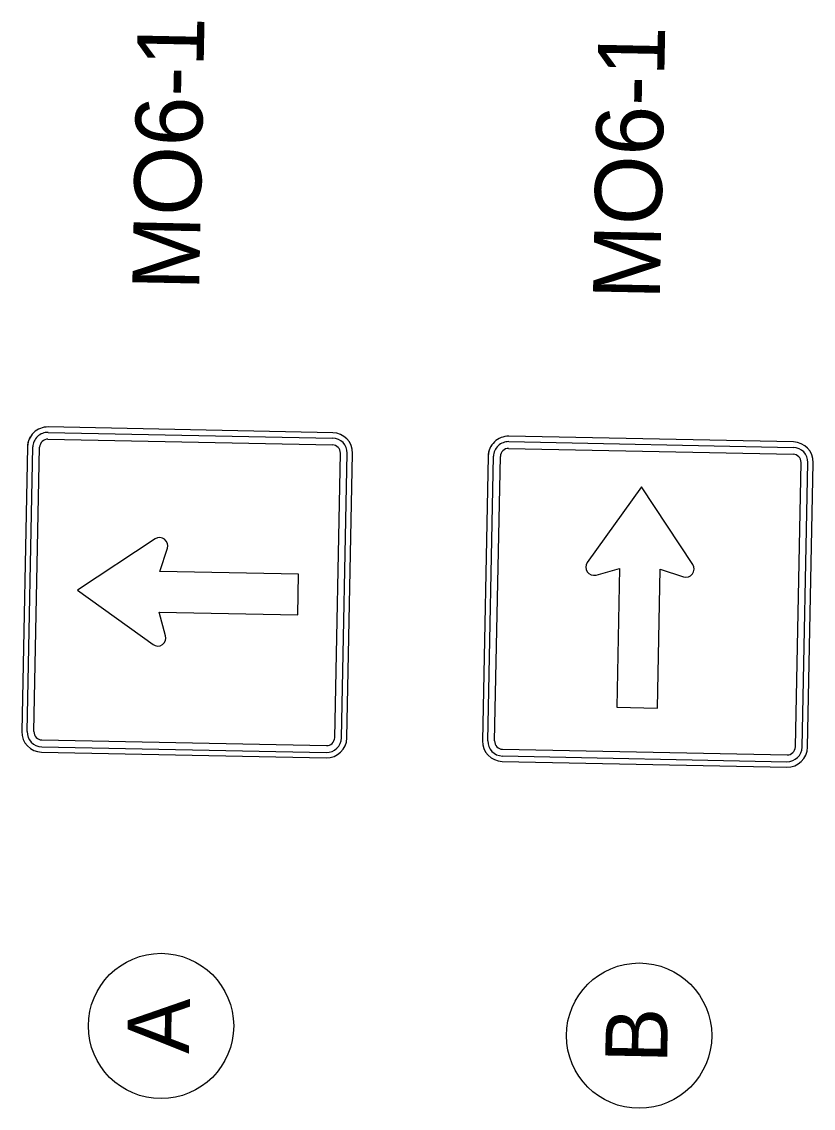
# Model space of a CAD drawing. Extents: x 327762 to 372975, y 127949 to 220470.
# Drawn here: x 357985 to 359582, y 211163 to 213355 of the extents above; entities that cross this region are included whole.
import ezdxf

# ---------------------------------------------------------------- set-up
doc = ezdxf.new("R2010")
doc.units = 0
doc.layers.add('CA-TEXT', color=7, linetype='Continuous')
doc.layers.add('P_SGN_Cell', color=7, linetype='Continuous')

msp = doc.modelspace()

# ---------------------------------------------------------------- linework, layer by layer
at = {"layer": 'CA-TEXT'}
for centre in [(358266, 211329.1), (359230.7, 211309.6)]:
    msp.add_circle(centre, 146.6, dxfattribs=at)
at = {"layer": 'P_SGN_Cell'}
for p, q in [((358038.1, 212526.8), (358612.2, 212515.2)), ((358612.4, 212526.2), (358038.3, 212537.7)), ((358037.8, 212513.1), (358611.9, 212501.6)), ((358967.7, 212508.1), (359541.8, 212496.5)), ((359542, 212507.5), (358967.9, 212519)), ((357996.5, 212497.5), (357984.9, 211923.5)), ((357995.9, 211923.2), (358007.4, 212497.3)), ((358009.5, 211923), (358021.1, 212497)), ((358616.4, 211910.8), (358628, 212484.8)), ((358630.1, 211910.5), (358641.6, 212484.6)), ((358641, 211910.3), (358652.6, 212484.3)), ((358967.4, 212494.4), (359541.5, 212482.8)), ((358926.1, 212478.8), (358914.5, 211904.7)), ((358925.4, 211904.5), (358937, 212478.6)), ((358939.1, 211904.3), (358950.7, 212478.3)), ((359546, 211892), (359557.6, 212466.1)), ((359559.7, 211891.8), (359571.2, 212465.8)), ((359570.6, 211891.5), (359582.2, 212465.6)), ((359235.6, 212417), (359126, 212264.4)), ((359338.9, 212260.1), (359235.6, 212417)), ((358254.2, 212311.7), (358097.3, 212208.4)), ((358263.6, 212246), (358278.8, 212293)), ((358543.7, 212240.4), (358263.6, 212246)), ((358542.1, 212158.4), (358543.7, 212240.4)), ((359143.8, 212239), (359191.3, 212252.3)), ((359191.3, 212252.3), (359185.6, 211972.2)), ((359267.6, 211970.5), (359273.3, 212250.7)), ((359273.3, 212250.7), (359320.2, 212235.5)), ((358097.3, 212208.4), (358249.9, 212098.8)), ((358275.3, 212116.5), (358262, 212164)), ((358262, 212164), (358542.1, 212158.4)), ((359185.6, 211972.2), (359267.6, 211970.5)), ((358025.3, 211892.6), (358599.4, 211881)), ((358025.6, 211906.2), (358599.7, 211894.7)), ((358025.1, 211881.6), (358599.2, 211870.1)), ((358954.9, 211873.9), (359529, 211862.3)), ((358955.2, 211887.5), (359529.3, 211876)), ((358954.7, 211862.9), (359528.8, 211851.4))]:
    msp.add_line(p, q, dxfattribs=at)
for centre, radius, start, end in [((358037.5, 212496.7), 41, 88.8468, 178.8468), ((358037.5, 212496.7), 30.1, 88.8468, 178.8468), ((358611.6, 212485.2), 41, 358.8468, 88.8468), ((358037.5, 212496.7), 41, 149.4503, 178.8468), ((358037.5, 212496.7), 16.4, 88.8468, 178.8468), ((358611.6, 212485.2), 30.1, 358.8468, 88.8468), ((358967.1, 212478), 41, 88.8468, 178.8468), ((358967.1, 212478), 30.1, 88.8468, 178.8468), ((359541.2, 212466.4), 41, 358.8468, 88.8468), ((358611.6, 212485.2), 16.4, 358.8468, 88.8468), ((358967.1, 212478), 41, 149.4503, 178.8468), ((358967.1, 212478), 16.4, 88.8468, 178.8468), ((359541.2, 212466.4), 16.4, 358.8468, 88.8468), ((359541.2, 212466.4), 30.1, 358.8468, 88.8468), ((358263.2, 212298), 16.4, 342.0442, 123.3765), ((359139.3, 212254.8), 16.4, 144.3172, 285.6494), ((359325.2, 212251.1), 16.4, 252.0442, 33.3765), ((358259.5, 212112.1), 16.4, 234.3172, 15.6494), ((358025.9, 211922.6), 41, 178.8468, 268.8468), ((358025.9, 211922.6), 30.1, 178.8468, 268.8468), ((358025.9, 211922.6), 16.4, 178.8468, 268.8468), ((358600, 211911.1), 41, 268.8468, 358.8468), ((358600, 211911.1), 30.1, 268.8468, 358.8468), ((358600, 211911.1), 16.4, 268.8468, 358.8468), ((358955.5, 211903.9), 41, 178.8468, 268.8468), ((358955.5, 211903.9), 30.1, 178.8468, 268.8468), ((358955.5, 211903.9), 16.4, 178.8468, 268.8468), ((359529.6, 211892.4), 41, 268.8468, 358.8468), ((359529.6, 211892.4), 30.1, 268.8468, 358.8468), ((359529.6, 211892.4), 16.4, 268.8468, 358.8468)]:
    msp.add_arc(centre, radius, start, end, dxfattribs=at)

# ---------------------------------------------------------------- texts
at = {"layer": 'CA-TEXT'}
for s, p in [('A', (358322.4, 211272.8)), ('B', (359287.1, 211253.4))]:
    msp.add_text(s, height=125, rotation=88.8468, dxfattribs=at).set_placement(p)
at = {"layer": 'P_SGN_Cell'}
for p in [(358342.8, 212812.3), (359272.4, 212793.6)]:
    msp.add_text('MO6-1', height=134.99, rotation=88.8468, dxfattribs=at).set_placement(p)

doc.saveas('drawing.dxf')
